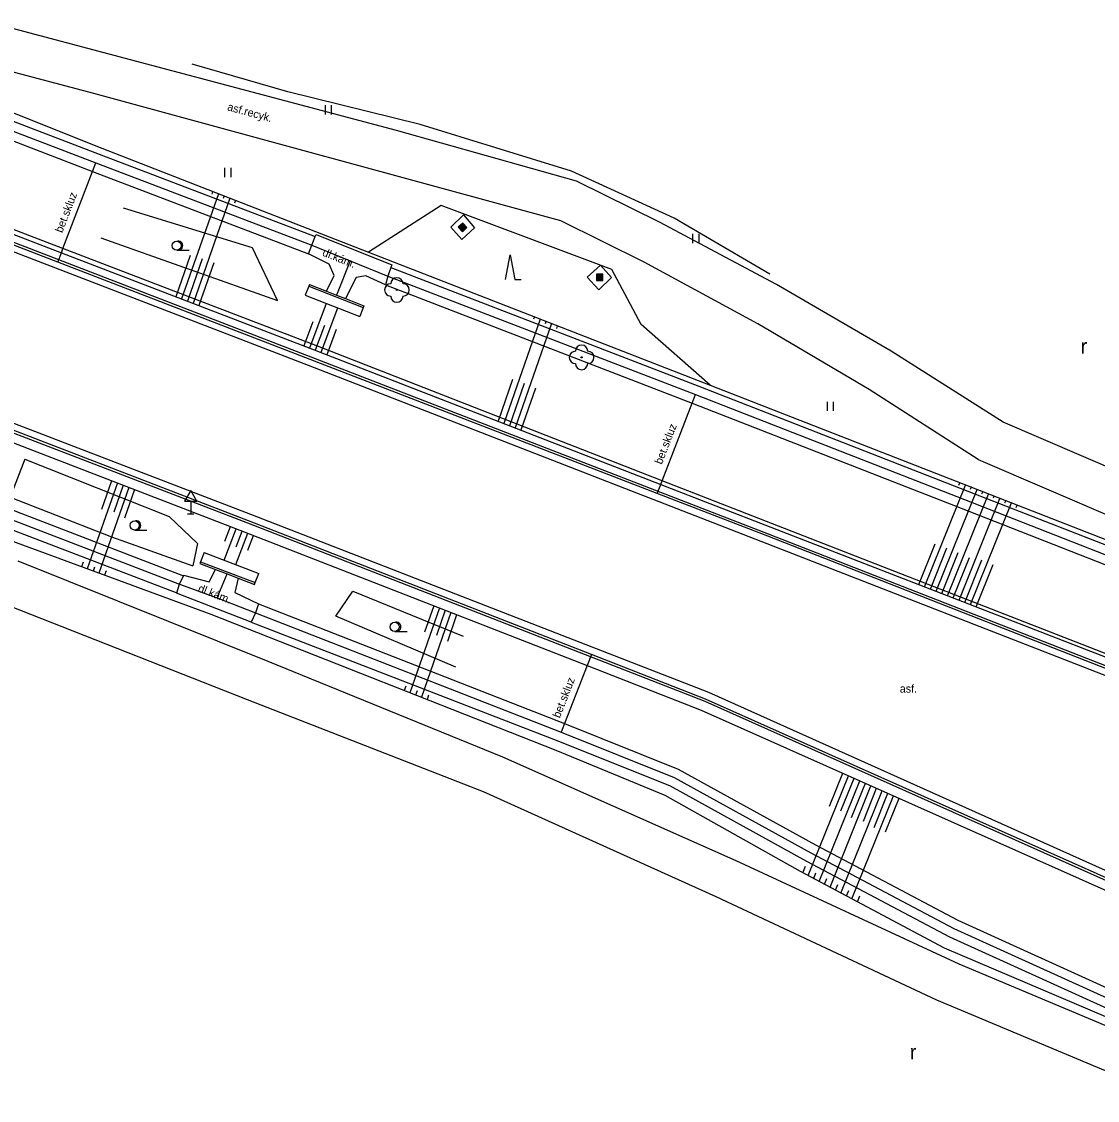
# Model space of a CAD drawing. Extents: x -539244 to -537359, y -1183785 to -1181851.
# Drawn here: x -539170.8 to -539083.4, y -1182568.8 to -1182481.2 of the extents above; entities that cross this region are included whole.
import ezdxf

# ---------------------------------------------------------------- set-up
doc = ezdxf.new("R2010")
doc.units = 0
for name, color, linetype in [('Vrstva 10', 7, 'Continuous'), ('Vrstva 11', 7, 'Continuous'), ('Vrstva 14', 7, 'Continuous'), ('Vrstva 15', 7, 'Continuous'), ('Vrstva 21', 7, 'Continuous'), ('Vrstva 22', 7, 'Continuous'), ('Vrstva 23', 7, 'Continuous'), ('Vrstva 25', 7, 'Continuous'), ('Vrstva 34', 7, 'Continuous'), ('Vrstva 36', 7, 'Continuous'), ('Vrstva 40', 7, 'Continuous'), ('Vrstva 7', 7, 'Continuous'), ('Vrstva 9', 7, 'Continuous')]:
    doc.layers.add(name, color=color, linetype=linetype)

msp = doc.modelspace()

# ---------------------------------------------------------------- linework, layer by layer
at = {"layer": 'Vrstva 10'}
for p, q in [((-539184.852, -1182494.684), (-539147.506, -1182509.059)), ((-539152.164, -1182521.178), (-539189.55, -1182506.804)), ((-539147.506, -1182509.059), (-539110.243, -1182523.535)), ((-539114.941, -1182535.641), (-539152.164, -1182521.178)), ((-539110.243, -1182523.535), (-539073.019, -1182538.046)), ((-539078.517, -1182551.973), (-539114.941, -1182535.641))]:
    msp.add_line(p, q, dxfattribs=at)
at = {"layer": 'Vrstva 11'}
for p, q in [((-539140.319, -1182490.011), (-539173.677, -1182481.156)), ((-539188.9, -1182482.563), (-539164.47, -1182491.933)), ((-539189.432, -1182483.965), (-539165.008, -1182493.334)), ((-539125.699, -1182494.111), (-539140.319, -1182490.011)), ((-539164.47, -1182491.933), (-539146.92, -1182498.608)), ((-539165.008, -1182493.334), (-539147.472, -1182500.013)), ((-539146.858, -1182498.449), (-539140.702, -1182500.907)), ((-539145.776, -1182500.849), (-539147.472, -1182500.013)), ((-539145.381, -1182501.761), (-539145.776, -1182500.849)), ((-539140.773, -1182501.13), (-539115.753, -1182510.749)), ((-539145.996, -1182503.045), (-539145.381, -1182501.761)), ((-539143.586, -1182501.945), (-539144.454, -1182503.647)), ((-539142.822, -1182501.807), (-539143.586, -1182501.945)), ((-539141.218, -1182502.525), (-539142.822, -1182501.807)), ((-539147.453, -1182502.638), (-539143.021, -1182504.368)), ((-539141.218, -1182502.525), (-539116.295, -1182512.147)), ((-539147.743, -1182503.383), (-539143.311, -1182505.113)), ((-539115.753, -1182510.749), (-539093.905, -1182519.274)), ((-539116.295, -1182512.147), (-539094.451, -1182520.672)), ((-539068.833, -1182523.236), (-539091.027, -1182513.683)), ((-539093.066, -1182516.707), (-539070.438, -1182526.434)), ((-539093.905, -1182519.274), (-539071.023, -1182528.23)), ((-539173.281, -1182520.147), (-539157.63, -1182526.149)), ((-539094.451, -1182520.672), (-539071.571, -1182529.626)), ((-539173.819, -1182521.547), (-539158.171, -1182527.548)), ((-539155.952, -1182524.264), (-539151.513, -1182525.966)), ((-539150.755, -1182533.124), (-539171.057, -1182524.969)), ((-539156.238, -1182525.011), (-539151.799, -1182526.713)), ((-539155.529, -1182526.647), (-539155.027, -1182525.636)), ((-539157.614, -1182526.107), (-539155.529, -1182526.647)), ((-539153.179, -1182526.345), (-539153.46, -1182527.502)), ((-539174.139, -1182527.657), (-539152.44, -1182536.201)), ((-539152.113, -1182529.931), (-539158.181, -1182527.573)), ((-539153.46, -1182527.502), (-539151.525, -1182528.439)), ((-539151.525, -1182528.439), (-539126.669, -1182538.162)), ((-539152.113, -1182529.931), (-539127.221, -1182539.556)), ((-539131.668, -1182540.878), (-539150.755, -1182533.124)), ((-539152.44, -1182536.201), (-539133.275, -1182543.658)), ((-539078.739, -1182552.449), (-539115.208, -1182536.163)), ((-539126.669, -1182538.162), (-539117.435, -1182541.857)), ((-539127.221, -1182539.556), (-539118.079, -1182543.215)), ((-539112.731, -1182549.302), (-539131.668, -1182540.878)), ((-539117.435, -1182541.857), (-539106.293, -1182547.997)), ((-539118.079, -1182543.215), (-539107.007, -1182549.317)), ((-539133.275, -1182543.658), (-539114.369, -1182552.204)), ((-539106.293, -1182547.997), (-539094.723, -1182554.126)), ((-539094.613, -1182557.691), (-539112.731, -1182549.302)), ((-539107.007, -1182549.317), (-539095.383, -1182555.474)), ((-539114.369, -1182552.204), (-539096.444, -1182560.596)), ((-539094.723, -1182554.126), (-539081.664, -1182560.035)), ((-539095.383, -1182555.474), (-539082.252, -1182561.415)), ((-539075.603, -1182565.677), (-539094.613, -1182557.691)), ((-539096.444, -1182560.596), (-539076.977, -1182568.755))]:
    msp.add_line(p, q, dxfattribs=at)
for points in [[(-539126.967, -1182497.335), (-539164.911, -1182487.005), (-539174.951, -1182484.341)], [(-539147.32, -1182508.584), (-539167.838, -1182500.684), (-539184.634, -1182494.217)], [(-539091.027, -1182513.683), (-539100.134, -1182507.923), (-539109.449, -1182502.505), (-539118.958, -1182497.436), (-539125.699, -1182494.111)], [(-539093.066, -1182516.707), (-539101.907, -1182511.029), (-539110.957, -1182505.692), (-539120.204, -1182500.703), (-539126.967, -1182497.335)], [(-539147.472, -1182500.013), (-539147.194, -1182499.306), (-539146.92, -1182498.608), (-539146.858, -1182498.449)], [(-539140.702, -1182500.907), (-539140.773, -1182501.13), (-539141.015, -1182501.84), (-539141.218, -1182502.525)], [(-539147.398, -1182502.498), (-539147.453, -1182502.638), (-539147.743, -1182503.383)], [(-539147.398, -1182502.498), (-539145.996, -1182503.045), (-539145.191, -1182503.359), (-539144.454, -1182503.647), (-539142.966, -1182504.228)], [(-539142.966, -1182504.228), (-539143.021, -1182504.368), (-539143.311, -1182505.113)], [(-539152.354, -1182521.681), (-539171.096, -1182514.47), (-539189.714, -1182507.307)], [(-539110.159, -1182522.951), (-539119.13, -1182519.483), (-539147.32, -1182508.584)], [(-539115.208, -1182536.163), (-539124.484, -1182532.547), (-539152.354, -1182521.681)], [(-539072.745, -1182537.585), (-539074.491, -1182536.902), (-539110.159, -1182522.951)], [(-539155.952, -1182524.264), (-539156.238, -1182525.011), (-539156.292, -1182525.151)], [(-539156.292, -1182525.151), (-539155.027, -1182525.636), (-539154.085, -1182525.998), (-539153.179, -1182526.345), (-539151.853, -1182526.853)], [(-539151.853, -1182526.853), (-539151.799, -1182526.713), (-539151.513, -1182525.966)], [(-539158.181, -1182527.573), (-539158.171, -1182527.548), (-539157.942, -1182526.833), (-539157.63, -1182526.149), (-539157.614, -1182526.107)], [(-539151.525, -1182528.439), (-539151.763, -1182529.161), (-539152.113, -1182529.931)]]:
    msp.add_lwpolyline(points, dxfattribs=at)
at = {"layer": 'Vrstva 14'}
for p, q in [((-539188.751, -1182481.664), (-539164.252, -1182491.445)), ((-539189.166, -1182483.264), (-539164.738, -1182492.634)), ((-539165.008, -1182493.334), (-539164.738, -1182492.634)), ((-539164.738, -1182492.634), (-539147.194, -1182499.306)), ((-539167.414, -1182499.584), (-539165.008, -1182493.334)), ((-539167.543, -1182499.92), (-539167.414, -1182499.584)), ((-539147.194, -1182499.306), (-539144.09, -1182500.581)), ((-539167.838, -1182500.684), (-539167.543, -1182499.92)), ((-539144.09, -1182500.581), (-539145.191, -1182503.359)), ((-539144.09, -1182500.581), (-539141.015, -1182501.84)), ((-539141.015, -1182501.84), (-539116.024, -1182511.448)), ((-539116.024, -1182511.448), (-539094.178, -1182519.973)), ((-539119.13, -1182519.483), (-539118.843, -1182518.74)), ((-539118.843, -1182518.74), (-539118.724, -1182518.433)), ((-539094.178, -1182519.973), (-539071.297, -1182528.928)), ((-539173.55, -1182520.847), (-539157.942, -1182526.833)), ((-539155.376, -1182529.294), (-539174.242, -1182522.361)), ((-539154.883, -1182527.938), (-539154.085, -1182525.998)), ((-539157.942, -1182526.833), (-539154.883, -1182527.938)), ((-539154.883, -1182527.938), (-539151.763, -1182529.161)), ((-539127.353, -1182540.331), (-539155.376, -1182529.294)), ((-539151.763, -1182529.161), (-539126.945, -1182538.859)), ((-539124.484, -1182532.547), (-539124.834, -1182533.448)), ((-539115.559, -1182537.064), (-539079.11, -1182553.293)), ((-539126.945, -1182538.859), (-539117.757, -1182542.536)), ((-539118.49, -1182543.985), (-539127.353, -1182540.331)), ((-539117.757, -1182542.536), (-539106.65, -1182548.657)), ((-539107.51, -1182550.158), (-539118.49, -1182543.985)), ((-539106.65, -1182548.657), (-539095.053, -1182554.8)), ((-539095.794, -1182556.401), (-539107.51, -1182550.158)), ((-539095.053, -1182554.8), (-539081.958, -1182560.725)), ((-539082.516, -1182562.06), (-539095.794, -1182556.401))]:
    msp.add_line(p, q, dxfattribs=at)
for points in [[(-539203.011, -1182486.282), (-539167.543, -1182499.92), (-539147.002, -1182507.818)], [(-539164.252, -1182491.445), (-539142.6, -1182499.87)], [(-539227.308, -1182493.872), (-539217.667, -1182497.582), (-539171.443, -1182515.371), (-539152.698, -1182522.585)], [(-539142.6, -1182499.87), (-539114.84, -1182510.69)], [(-539147.002, -1182507.818), (-539118.843, -1182518.74), (-539074.158, -1182536.072), (-539072.523, -1182536.706)], [(-539114.84, -1182510.69), (-539022.548, -1182546.677)], [(-539118.724, -1182518.433), (-539116.295, -1182512.147), (-539116.024, -1182511.448)], [(-539152.698, -1182522.585), (-539124.834, -1182533.448), (-539115.559, -1182537.064)], [(-539124.834, -1182533.448), (-539126.669, -1182538.162), (-539126.945, -1182538.859)]]:
    msp.add_lwpolyline(points, dxfattribs=at)
at = {"layer": 'Vrstva 15'}
for p, q in [((-539154.79, -1182495.133), (-539157.775, -1182503.676)), ((-539155.256, -1182494.951), (-539155.332, -1182495.167)), ((-539154.324, -1182495.315), (-539154.396, -1182495.521)), ((-539153.857, -1182495.497), (-539156.841, -1182504.035)), ((-539153.391, -1182495.678), (-539153.468, -1182495.899)), ((-539157.075, -1182500.156), (-539158.242, -1182503.496)), ((-539156.11, -1182500.428), (-539157.308, -1182503.855)), ((-539155.162, -1182500.746), (-539156.374, -1182504.214)), ((-539146.031, -1182504.051), (-539147.39, -1182507.669)), ((-539145.099, -1182504.415), (-539146.458, -1182508.029)), ((-539147.126, -1182505.543), (-539147.857, -1182507.489)), ((-539146.165, -1182505.83), (-539146.924, -1182507.848)), ((-539128.653, -1182505.321), (-539131.606, -1182513.79)), ((-539127.72, -1182505.684), (-539130.673, -1182514.151)), ((-539129.118, -1182505.139), (-539129.181, -1182505.321)), ((-539128.186, -1182505.502), (-539128.251, -1182505.69)), ((-539127.254, -1182505.866), (-539127.325, -1182506.068)), ((-539145.218, -1182506.153), (-539145.991, -1182508.21)), ((-539130.888, -1182510.213), (-539132.072, -1182513.609)), ((-539129.944, -1182510.543), (-539131.139, -1182513.971)), ((-539129.014, -1182510.913), (-539130.207, -1182514.332)), ((-539162.998, -1182518.621), (-539165.436, -1182525.597)), ((-539162.064, -1182518.98), (-539164.497, -1182525.942)), ((-539163.465, -1182518.442), (-539164.281, -1182520.776)), ((-539162.531, -1182518.801), (-539163.293, -1182520.98)), ((-539097.417, -1182527.051), (-539094.087, -1182518.793)), ((-539094.63, -1182518.802), (-539094.553, -1182518.612)), ((-539093.684, -1182519.132), (-539093.621, -1182518.975)), ((-539161.598, -1182519.16), (-539162.406, -1182521.474)), ((-539096.484, -1182527.412), (-539093.155, -1182519.156)), ((-539095.552, -1182527.774), (-539092.224, -1182519.519)), ((-539094.62, -1182528.135), (-539091.292, -1182519.882)), ((-539092.754, -1182519.495), (-539092.691, -1182519.338)), ((-539091.811, -1182519.834), (-539091.757, -1182519.701)), ((-539093.687, -1182528.497), (-539090.36, -1182520.246)), ((-539090.89, -1182520.223), (-539090.826, -1182520.064)), ((-539089.968, -1182520.61), (-539089.894, -1182520.427)), ((-539154.318, -1182524.89), (-539153.331, -1182522.341)), ((-539154.26, -1182523.357), (-539153.797, -1182522.162)), ((-539153.356, -1182523.792), (-539152.864, -1182522.521)), ((-539153.385, -1182525.248), (-539152.398, -1182522.702)), ((-539152.396, -1182524.079), (-539151.933, -1182522.883)), ((-539097.883, -1182526.87), (-539096.552, -1182523.568)), ((-539096.95, -1182527.231), (-539095.602, -1182523.889)), ((-539096.019, -1182527.593), (-539094.682, -1182524.277)), ((-539165.775, -1182525.052), (-539165.905, -1182525.425)), ((-539095.086, -1182527.955), (-539093.762, -1182524.671)), ((-539094.153, -1182528.316), (-539092.761, -1182524.863)), ((-539164.855, -1182525.45), (-539164.967, -1182525.77)), ((-539163.906, -1182525.764), (-539164.028, -1182526.114)), ((-539093.221, -1182528.678), (-539091.836, -1182525.242)), ((-539137.296, -1182528.589), (-539138.045, -1182530.737)), ((-539136.83, -1182528.771), (-539139.23, -1182535.653)), ((-539135.898, -1182529.135), (-539138.299, -1182536.02)), ((-539136.364, -1182528.953), (-539137.083, -1182531.014)), ((-539135.432, -1182529.316), (-539136.189, -1182531.487)), ((-539139.569, -1182535.106), (-539139.696, -1182535.47)), ((-539138.65, -1182535.508), (-539138.765, -1182535.836)), ((-539137.71, -1182535.848), (-539137.834, -1182536.203)), ((-539106.871, -1182550.498), (-539103.601, -1182542.388)), ((-539105.143, -1182544.873), (-539104.059, -1182542.185)), ((-539104.212, -1182545.24), (-539103.144, -1182542.592)), ((-539105.983, -1182550.971), (-539102.687, -1182542.795)), ((-539105.096, -1182551.444), (-539101.773, -1182543.202)), ((-539103.356, -1182545.792), (-539102.23, -1182542.999)), ((-539102.391, -1182546.073), (-539101.316, -1182543.406)), ((-539104.209, -1182551.917), (-539100.859, -1182543.609)), ((-539103.321, -1182552.39), (-539099.945, -1182544.016)), ((-539101.524, -1182546.596), (-539100.402, -1182543.813)), ((-539100.585, -1182546.942), (-539099.487, -1182544.22)), ((-539107.315, -1182550.262), (-539107.097, -1182549.721)), ((-539106.427, -1182550.735), (-539106.242, -1182550.277)), ((-539105.54, -1182551.208), (-539105.351, -1182550.739)), ((-539104.652, -1182551.681), (-539104.467, -1182551.221)), ((-539103.764, -1182552.154), (-539103.583, -1182551.704)), ((-539102.876, -1182552.627), (-539102.678, -1182552.135))]:
    msp.add_line(p, q, dxfattribs=at)
at = {"layer": 'Vrstva 21'}
for points in [[(-539114.84, -1182510.69), (-539120.44, -1182505.75), (-539122.82, -1182501.29), (-539136.69, -1182496.08), (-539142.6, -1182499.87)], [(-539164.34, -1182498.72), (-539149.99, -1182503.81), (-539152.01, -1182499.54), (-539162.5, -1182496.32)], [(-539170.5, -1182516.7), (-539171.698, -1182519.779), (-539163.47, -1182522.98), (-539156.86, -1182525.35)], [(-539170.5, -1182516.7), (-539158.78, -1182521.35), (-539156.49, -1182523.54), (-539156.86, -1182525.35)], [(-539135.51, -1182533.58), (-539145.26, -1182529.44), (-539143.86, -1182527.4), (-539134.904, -1182531.052)]]:
    msp.add_lwpolyline(points, dxfattribs=at)
at = {"layer": 'Vrstva 22'}
for centre in [(-539140.29, -1182502.95), (-539125.28, -1182508.42)]:
    msp.add_circle(centre, 0.05, dxfattribs=at)
for centre, start, end in [((-539140.29, -1182502.45), 0, 180), ((-539140.79, -1182502.95), 90, 270), ((-539139.79, -1182502.95), 270, 90), ((-539140.29, -1182503.45), 180, 0), ((-539125.28, -1182507.92), 0, 180), ((-539125.78, -1182508.42), 90, 270), ((-539124.78, -1182508.42), 270, 90), ((-539125.28, -1182508.92), 180, 0)]:
    msp.add_arc(centre, 0.5, start, end, dxfattribs=at)
at = {"layer": 'Vrstva 23'}
msp.add_lwpolyline([(-539109.98, -1182501.67), (-539117.75, -1182497.13), (-539126.11, -1182493.29), (-539138.4, -1182489.51), (-539149.16, -1182486.87), (-539156.93, -1182484.61)], dxfattribs=at)
at = {"layer": 'Vrstva 25'}
for points in [[(-539135.303, -1182497.856), (-539134.964, -1182498.223), (-539134.597, -1182497.884), (-539134.936, -1182497.517)], [(-539135.233, -1182497.859), (-539134.961, -1182498.153), (-539134.667, -1182497.881), (-539134.939, -1182497.587)], [(-539135.162, -1182497.861), (-539134.959, -1182498.082), (-539134.738, -1182497.879), (-539134.941, -1182497.658)], [(-539135.091, -1182497.864), (-539134.956, -1182498.011), (-539134.809, -1182497.876), (-539134.944, -1182497.729)], [(-539135.021, -1182497.867), (-539134.953, -1182497.941), (-539134.879, -1182497.873), (-539134.947, -1182497.799)], [(-539124.061, -1182502.17), (-539123.561, -1182502.17), (-539123.561, -1182501.67), (-539124.061, -1182501.67)], [(-539124.011, -1182502.12), (-539123.611, -1182502.12), (-539123.611, -1182501.72), (-539124.011, -1182501.72)], [(-539123.961, -1182502.07), (-539123.661, -1182502.07), (-539123.661, -1182501.77), (-539123.961, -1182501.77)], [(-539123.911, -1182502.02), (-539123.711, -1182502.02), (-539123.711, -1182501.82), (-539123.911, -1182501.82)], [(-539123.861, -1182501.97), (-539123.761, -1182501.97), (-539123.761, -1182501.87), (-539123.861, -1182501.87)]]:
    msp.add_lwpolyline(points, close=True, dxfattribs=at)
at = {"layer": 'Vrstva 34'}
for p, q in [((-539157.04, -1182520.102), (-539157.04, -1182521.12)), ((-539157.29, -1182521.12), (-539156.79, -1182521.12))]:
    msp.add_line(p, q, dxfattribs=at)
msp.add_lwpolyline([(-539157.54, -1182520.102), (-539156.54, -1182520.102), (-539157.04, -1182519.236)], close=True, dxfattribs=at)
at = {"layer": 'Vrstva 36'}
for p, q in [((-539146.091, -1182488.701), (-539146.091, -1182487.951)), ((-539145.591, -1182488.701), (-539145.591, -1182487.951)), ((-539154.262, -1182493.795), (-539154.262, -1182493.045)), ((-539153.762, -1182493.795), (-539153.762, -1182493.045)), ((-539116.235, -1182499.148), (-539116.235, -1182498.398)), ((-539115.735, -1182499.148), (-539115.735, -1182498.398)), ((-539158.176, -1182499.725), (-539157.176, -1182499.725)), ((-539105.309, -1182512.769), (-539105.309, -1182512.019)), ((-539104.809, -1182512.769), (-539104.809, -1182512.019)), ((-539161.59, -1182522.441), (-539160.59, -1182522.441)), ((-539140.463, -1182530.675), (-539139.463, -1182530.675))]:
    msp.add_line(p, q, dxfattribs=at)
msp.add_lwpolyline([(-539131.453, -1182502.098), (-539131.078, -1182500.098), (-539130.703, -1182502.098), (-539130.203, -1182502.098)], dxfattribs=at)
for centre in [(-539158.176, -1182499.349), (-539161.59, -1182522.065), (-539140.463, -1182530.3)]:
    msp.add_circle(centre, 0.375, dxfattribs=at)
for centre in [(-539158.051, -1182499.349), (-539161.465, -1182522.065), (-539140.338, -1182530.3)]:
    msp.add_arc(centre, 0.375, 260.40593, 99.59407, dxfattribs=at)
at = {"layer": 'Vrstva 7'}
for points in [[(-539146.861, -1182507.464), (-539167.414, -1182499.584), (-539202.867, -1182485.991)], [(-539134.88, -1182496.84), (-539133.97, -1182497.89), (-539135.01, -1182498.84), (-539135.9, -1182497.86), (-539134.88, -1182496.84)], [(-539123.746, -1182500.939), (-539124.82, -1182501.91), (-539123.88, -1182502.95), (-539122.85, -1182501.93), (-539123.746, -1182500.939)], [(-539072.384, -1182536.499), (-539074.066, -1182535.843), (-539118.724, -1182518.433), (-539146.861, -1182507.464)]]:
    msp.add_lwpolyline(points, dxfattribs=at)
at = {"layer": 'Vrstva 9'}
for p, q in [((-539147.248, -1182508.397), (-539184.562, -1182494.03)), ((-539189.786, -1182507.494), (-539152.426, -1182521.868)), ((-539110.087, -1182522.764), (-539147.248, -1182508.397)), ((-539152.426, -1182521.868), (-539115.281, -1182536.349)), ((-539072.672, -1182537.399), (-539110.086, -1182522.765)), ((-539115.281, -1182536.349), (-539078.821, -1182552.632))]:
    msp.add_line(p, q, dxfattribs=at)

# ---------------------------------------------------------------- texts
at = {"layer": 'Vrstva 36'}
for p in [(-539084.743, -1182508.117), (-539098.617, -1182565.422)]:
    msp.add_text('r', height=1.2, dxfattribs=at).set_placement(p)
at = {"layer": 'Vrstva 40'}
for s, rotation, p in [('asf.recyk.', 344.86103, (-539154.109, -1182488.35)), ('bet.skluz', 68.93864, (-539167.478, -1182498.358)), ('dl.kám.', 338.2339, (-539146.396, -1182500.141)), ('bet.skluz', 68.86555, (-539118.768, -1182517.16)), ('dl.kám.', 338.76408, (-539156.497, -1182527.423)), ('bet.skluz', 68.69957, (-539127.052, -1182537.756))]:
    msp.add_text(s, height=0.65, rotation=rotation, dxfattribs=at).set_placement(p)
msp.add_text('asf.', height=0.65, dxfattribs=at).set_placement((-539099.431, -1182535.644))

doc.saveas('drawing.dxf')
